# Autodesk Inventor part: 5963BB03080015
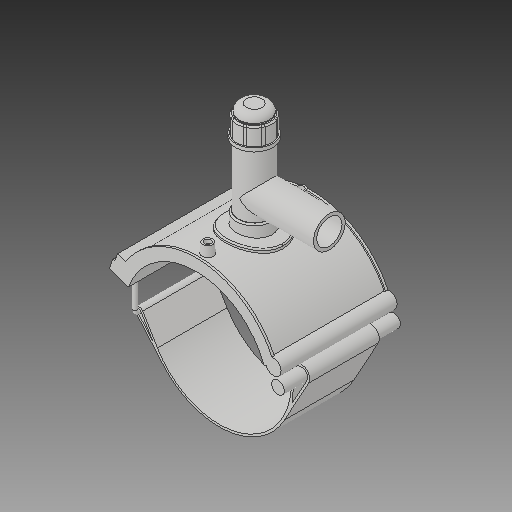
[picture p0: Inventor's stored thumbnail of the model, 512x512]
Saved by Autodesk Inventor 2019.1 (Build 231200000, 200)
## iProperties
Created: 2017-07
Part Number: 5963BB03080015
Material: Generic
Description: PLASSON TAPPING SADDLE 8''IPS x 1 1/2''IPS
Document SubType Name: Modeling
Designer: KIM
Mass: 1712.7 g
Surface Area: 2671.49 cm^2
Volume: 1712.7 cm^3
Density: 1 g/cm^3
Appearance: Default
Author: KIM
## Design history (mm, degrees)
derived "5963B.ipt"
feature "Solid1::5963B.ipt"
feature "Solid2::5963B.ipt"
feature "Solid4::5963B.ipt"
feature "Solid5::5963B.ipt"
tag "TaggingFeature1" dims "d_" = 218.7
body "Solid1"
body "Solid2"
other parameters: "B_" = 179.832, "L_" = 176.022, "d_t" = 6, "H_2" = 177.038, "H_1" = 65.024, "d_1" = 48.1, "H_" = 114.046, "d1" = 249.318, "d148" = 3.2805, "d160" = 3.2805, "d169" = 3.2805, "d192" = 6.1236, "d0" = 218.7, "d2" = 269.748, "d3" = 54.675, "d4" = 176.022, "d5" = 0, "d6" = 0.1, "d8" = 0, "d19" = 6, "d20" = 6, "d21" = 105.6132, "d23" = 0, "d24" = 52.8066, "d26" = 0, "d29" = 3, "d30" = 72.9, "d31" = 6, "d32" = 0, "d33" = 0, "d34" = 0.6, "d40" = 129.64536, "d41" = 87.48, "d43" = 0, "d45" = 0, "d47" = 230.2722, "d70" = 15, "d72" = 0, "d73" = 6, "d75" = 5, "d76" = 0, "d77" = 10.935, "d78" = 139.35, "d79" = 15, "d80" = 70.4088, "d82" = 5 deg, "d84" = 4, "d85" = 14, "d86" = 0, "d87" = 3, "d88" = 0, "d89" = 1, "d90" = 1, "d91" = 140.8176, "d92" = 0, "d93" = 0.5, "d94" = 115.10526, "d96" = 254.30436, "d97" = 3.52044, "d98" = 0, "d102" = 2.187, "d120" = 140 deg, "d121" = 24.228, "d122" = 20 deg, "d123" = 498.636, "d124" = 149.5908, "d126" = 0, "d143" = 225.261, "d145" = 23.55231, "d149" = 3.2805, "d150" = 25.90754, "d153" = 176.022, "d154" = 0, "d156" = 124.659, "d157" = 160 deg, "d159" = 6.1236, "d161" = 3.2805, "d162" = 105.6132, "d163" = 0, "d164" = 109.35, "d167" = 21.87, "d168" = 121.61854, "d170" = 3.2805, "d172" = 0, "d173" = 1, "d175" = 109.35, "d176" = 20 deg, "d177" = 15.309, "d178" = 30.618, "d180" = 0, "d183" = 12.2472, "d184" = 12.2472, "d185" = 57.20715, "d186" = 57.20715, "d187" = 124.659, "d188" = 9.1854, "d189" = 15.309, "d190" = 0, "d191" = 186.9885, "d193" = 6.1236, "d194" = 6.16077, "d195" = 90 deg, "d197" = 0, "d199" = 0, "d200" = 15.309, "d202" = 0, "d203" = 177.038, "d204" = 54.0189, "d205" = 39.8034, "d206" = 48.3327, "d207" = 132.7785, "d208" = 138.08964, "d209" = 164.64534, "d210" = 48.90132, "d211" = 56.862, "d212" = 45.4896, "d213" = 36.8766, "d216" = 0, "d217" = 21.87, "d218" = 10.935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
